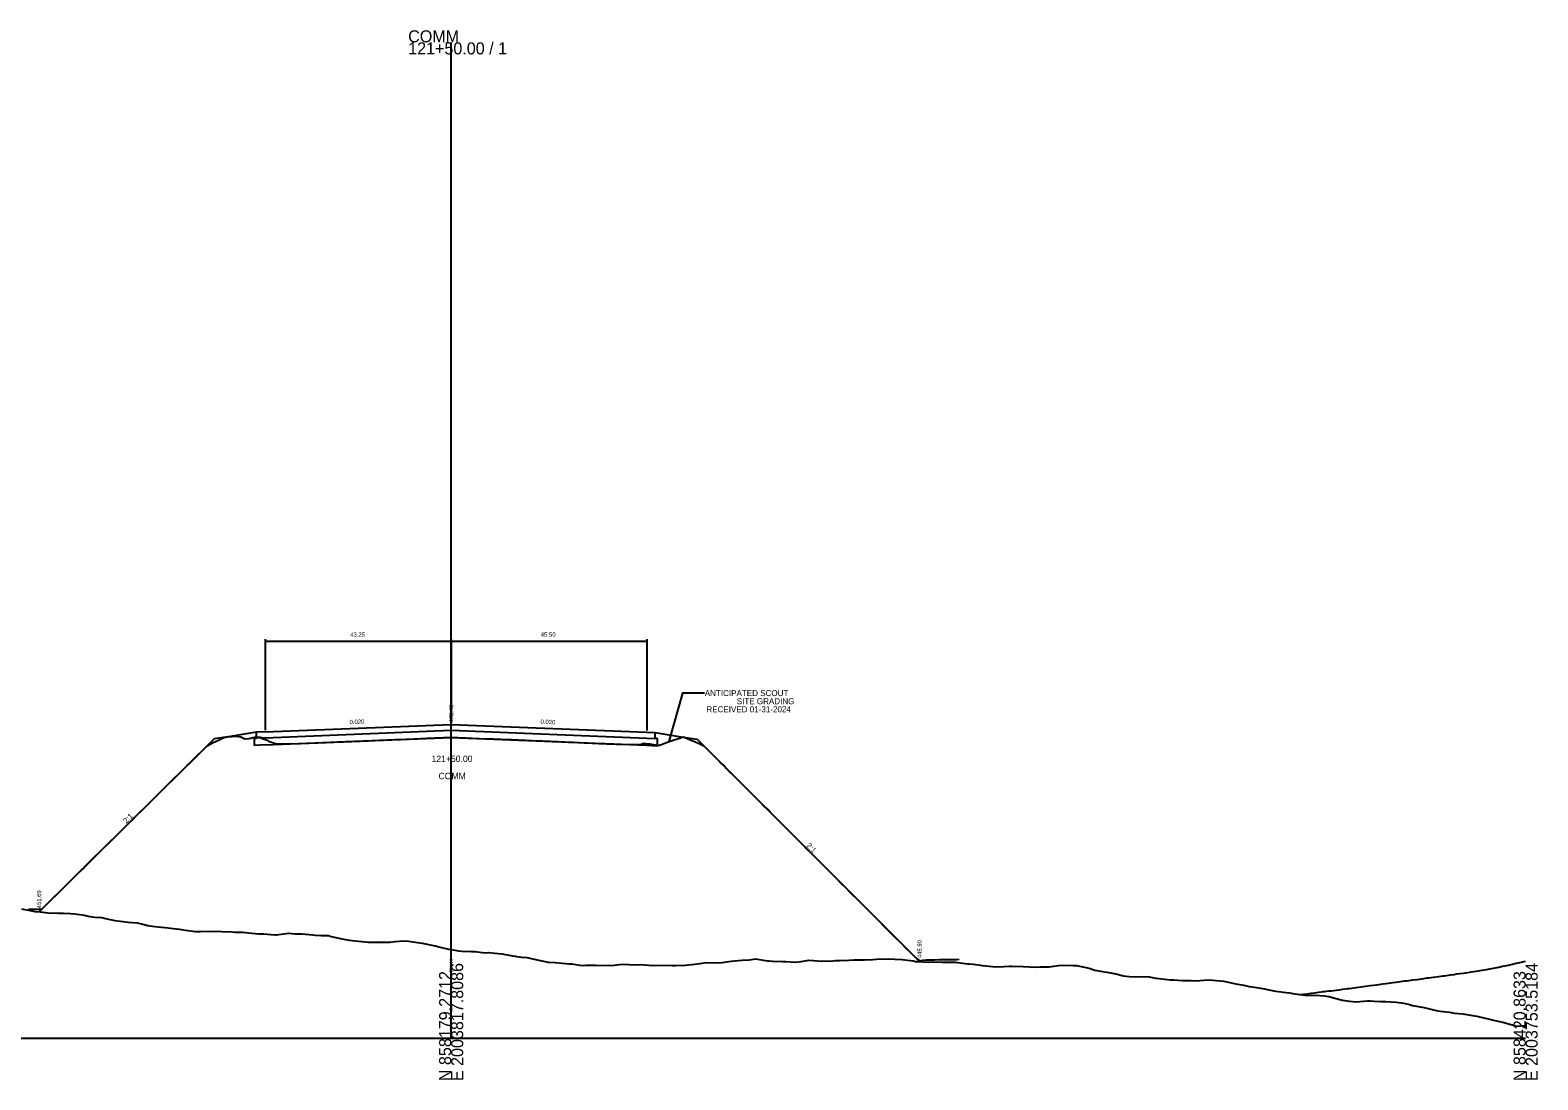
# Model space of a CAD drawing. Extents: x 2058594 to 2062449, y 841632 to 858028.
# Drawn here: x 2061098.6 to 2061449.4, y 855453.8 to 855698 of the extents above; entities that cross this region are included whole.
import ezdxf

# ---------------------------------------------------------------- set-up
doc = ezdxf.new("R2010")
doc.units = 0
for name, color, linetype in [('RD_DDB_Profile_Elev', 7, 'Continuous'), ('RD_GPK_XS_Cell', 7, 'Continuous'), ('RD_XS_Base', 7, 'Continuous'), ('RD_XS_EarthShd', 7, 'Continuous'), ('RD_XS_EwShp1', 7, 'Continuous'), ('RD_XS_ExGround', 7, 'Continuous'), ('RD_XS_Pave', 7, 'Continuous'), ('RD_XS_PaveShd', 7, 'Continuous'), ('RD_XS_TieSlope', 7, 'Continuous'), ('RD_XS_TX_Ditch', 7, 'Continuous'), ('RD_XS_TX_Elev_EX', 7, 'Continuous'), ('RD_XS_TX_Elev_PR', 7, 'Continuous'), ('RD_XS_TX_Misc', 7, 'Continuous'), ('RD_XS_TX_Slope', 7, 'Continuous'), ('RD_XS_TX_Station', 7, 'Continuous')]:
    doc.layers.add(name, color=color, linetype=linetype)

msp = doc.modelspace()

# ---------------------------------------------------------------- linework, layer by layer
at = {"layer": 'RD_DDB_Profile_Elev'}
for points in [[(2061255.47, 855543.83), (2061250.35, 855543.83), (2061247.13, 855532.52)], [(2061098.16, 855493.53), (2061099.26, 855493.53), (2061100.12, 855493.53), (2061101.24, 855493.53), (2061102.3, 855494.52), (2061103.27, 855495.53), (2061104.07, 855496.32), (2061105.29, 855497.53), (2061107.32, 855499.53), (2061108.7, 855500.89), (2061109.34, 855501.53), (2061110.86, 855503.03), (2061111.37, 855503.53), (2061113.4, 855505.53), (2061114.93, 855507.04), (2061115.42, 855507.53), (2061117.45, 855509.53), (2061119.47, 855511.53), (2061120.57, 855512.61), (2061121.5, 855513.53), (2061122.43, 855514.43), (2061123.52, 855515.53), (2061124.45, 855516.44), (2061125.55, 855517.53), (2061126.22, 855518.18), (2061127.58, 855519.53), (2061129.6, 855521.53), (2061131.63, 855523.53), (2061133.65, 855525.53), (2061135.11, 855526.97), (2061135.68, 855527.53), (2061136.61, 855528.45), (2061137.7, 855529.53), (2061139.73, 855531.53), (2061141.16, 855532.32), (2061142.21, 855532.8), (2061142.97, 855533.19), (2061143.79, 855533.53), (2061144.09, 855533.58), (2061144.48, 855533.65), (2061146.62, 855533.78), (2061147, 855533.71), (2061147.56, 855533.6), (2061148.51, 855533.13), (2061149.46, 855533.27), (2061149.88, 855533.35), (2061150.4, 855533.45), (2061150.82, 855533.53), (2061152.05, 855533.53), (2061152.7, 855533.15), (2061153.53, 855532.9), (2061154.04, 855532.66), (2061155.86, 855532.04), (2061156.74, 855532.02), (2061158.41, 855532), (2061161.08, 855532.07), (2061161.45, 855532.09), (2061162.89, 855532.15), (2061163.4, 855532.17), (2061164.76, 855532.22), (2061165.41, 855532.25), (2061166.62, 855532.3), (2061167.4, 855532.33), (2061168.41, 855532.37), (2061169.27, 855532.41), (2061170.06, 855532.44), (2061170.58, 855532.46), (2061171.47, 855532.5), (2061171.93, 855532.52), (2061172.8, 855532.56), (2061173.37, 855532.58), (2061174.01, 855532.61), (2061174.77, 855532.64), (2061175.34, 855532.66), (2061176, 855532.69), (2061176.59, 855532.72), (2061177.24, 855532.74), (2061178.09, 855532.78), (2061178.7, 855532.8), (2061179.78, 855532.85), (2061180.32, 855532.87), (2061181.61, 855532.92), (2061182.06, 855532.94), (2061183.5, 855533), (2061184.15, 855533.03), (2061186.05, 855533.11), (2061187.79, 855533.18), (2061189.45, 855533.25), (2061190.86, 855533.3), (2061191.72, 855533.34), (2061192.15, 855533.36), (2061192.75, 855533.38), (2061193.33, 855533.4), (2061194.09, 855533.42), (2061194.7, 855533.44), (2061195.76, 855533.47), (2061196.95, 855533.47), (2061198.01, 855533.45), (2061198.75, 855533.42), (2061199.95, 855533.38), (2061201.43, 855533.32), (2061203.04, 855533.26), (2061204.67, 855533.2), (2061206.45, 855533.13), (2061208.05, 855533.07), (2061209.17, 855533.03), (2061209.54, 855533.01), (2061210.44, 855532.98), (2061210.87, 855532.96), (2061211.52, 855532.93), (2061212.12, 855532.91), (2061212.61, 855532.89), (2061213.39, 855532.85), (2061213.91, 855532.83), (2061214.81, 855532.79), (2061215.35, 855532.77), (2061216.3, 855532.73), (2061216.83, 855532.71), (2061217.78, 855532.67), (2061218.26, 855532.65), (2061218.65, 855532.63), (2061219.56, 855532.59), (2061219.99, 855532.58), (2061220.59, 855532.55), (2061221.43, 855532.51), (2061222.2, 855532.48), (2061222.94, 855532.45), (2061223.85, 855532.41), (2061224.47, 855532.39), (2061224.97, 855532.36), (2061225.99, 855532.32), (2061226.34, 855532.31), (2061227.45, 855532.26), (2061227.78, 855532.25), (2061228.2, 855532.23), (2061229.32, 855532.18), (2061229.78, 855532.16), (2061230.86, 855532.12), (2061231.32, 855532.1), (2061232.29, 855532.06), (2061232.72, 855532.04), (2061233.49, 855532.01), (2061234, 855531.99), (2061234.38, 855531.97), (2061234.98, 855531.95), (2061235.82, 855531.91), (2061236.13, 855531.9), (2061237.37, 855531.85), (2061240.74, 855531.89), (2061241.37, 855532.18), (2061241.84, 855532.11), (2061242.75, 855531.97), (2061244.74, 855531.61), (2061245.11, 855531.75), (2061245.46, 855531.87), (2061246.58, 855532.31), (2061247.67, 855532.73), (2061250.54, 855533.63), (2061252.32, 855532.89), (2061252.63, 855532.74), (2061252.97, 855532.59), (2061254.2, 855532.05), (2061254.66, 855531.83), (2061255.29, 855531.53), (2061256.17, 855530.68), (2061256.56, 855530.28), (2061257.29, 855529.53), (2061258.12, 855528.73), (2061258.51, 855528.33), (2061259.29, 855527.53), (2061260.08, 855526.78), (2061260.46, 855526.38), (2061261.29, 855525.53), (2061262.04, 855524.81), (2061262.42, 855524.41), (2061263.29, 855523.53), (2061264.01, 855522.84), (2061264.4, 855522.44), (2061265.29, 855521.53), (2061266.25, 855520.59), (2061267.29, 855519.53), (2061268.45, 855518.39), (2061269.29, 855517.53), (2061270.39, 855516.46), (2061271.29, 855515.53), (2061272.04, 855514.81), (2061273.29, 855513.53), (2061274.46, 855512.4), (2061275.29, 855511.53), (2061276.23, 855510.62), (2061277.29, 855509.53), (2061278.27, 855508.57), (2061279.29, 855507.53), (2061280.3, 855506.54), (2061281.29, 855505.53), (2061282.24, 855504.6), (2061283.29, 855503.53), (2061284.27, 855502.57), (2061285.29, 855501.53), (2061286.12, 855500.72), (2061287.29, 855499.53), (2061288.33, 855498.49), (2061289.29, 855497.53), (2061291.29, 855495.53), (2061293.29, 855493.53), (2061295.29, 855491.53), (2061295.92, 855490.9), (2061297.29, 855489.53), (2061299.29, 855487.53), (2061301.29, 855485.53), (2061302.26, 855484.56), (2061303.29, 855483.53), (2061304.69, 855482.15), (2061305.54, 855481.53), (2061306.29, 855481.66), (2061307.03, 855481.72), (2061308.03, 855481.73), (2061309, 855481.79), (2061310.13, 855481.8), (2061311.24, 855481.81), (2061312.3, 855481.8), (2061313.04, 855481.83), (2061313.58, 855481.85), (2061314.07, 855481.87), (2061314.73, 855481.89)], [(2061393.65, 855473.71), (2061395.77, 855473.88), (2061396.15, 855473.93), (2061396.64, 855474), (2061396.98, 855474.03), (2061397.49, 855474.11), (2061397.93, 855474.17), (2061398.34, 855474.21), (2061398.91, 855474.28), (2061399.4, 855474.35), (2061399.83, 855474.39), (2061400.2, 855474.43), (2061400.83, 855474.51), (2061401.25, 855474.56), (2061401.9, 855474.65), (2061402.54, 855474.73), (2061403.12, 855474.8), (2061403.98, 855474.91), (2061405.14, 855475.07), (2061405.52, 855475.12), (2061407.12, 855475.33), (2061408.73, 855475.54), (2061410.36, 855475.76), (2061411.87, 855475.97), (2061412.84, 855476.1), (2061413.29, 855476.16), (2061414.02, 855476.26), (2061414.64, 855476.34), (2061415.14, 855476.41), (2061415.58, 855476.46), (2061416.39, 855476.57), (2061416.89, 855476.63), (2061417.87, 855476.77), (2061418.36, 855476.83), (2061418.81, 855476.89), (2061419.85, 855477.03), (2061420.19, 855477.07), (2061421.24, 855477.21), (2061422.39, 855477.37), (2061423.22, 855477.48), (2061423.59, 855477.53), (2061424.01, 855477.58), (2061425.06, 855477.72), (2061426.27, 855477.88), (2061427.3, 855478.02), (2061427.62, 855478.06), (2061428.58, 855478.19), (2061429.05, 855478.26), (2061429.89, 855478.37), (2061430.53, 855478.47), (2061431.22, 855478.56), (2061432.02, 855478.68), (2061432.55, 855478.76), (2061433.5, 855478.9), (2061433.85, 855478.96), (2061435.11, 855479.15), (2061436.37, 855479.36), (2061437.4, 855479.53), (2061438.19, 855479.66), (2061439.06, 855479.83), (2061439.91, 855480), (2061440.26, 855480.07), (2061441.14, 855480.25), (2061441.74, 855480.38), (2061442.52, 855480.55), (2061443.44, 855480.75), (2061444.01, 855480.87), (2061445.56, 855481.2), (2061446.51, 855481.41)]]:
    msp.add_lwpolyline(points, dxfattribs=at)
at = {"layer": 'RD_GPK_XS_Cell'}
for p, q in [((2061196.51, 855463.53), (2061196.51, 855695.2)), ((2060946.51, 855463.53), (2061196.51, 855463.53)), ((2061196.51, 855463.53), (2061446.51, 855463.53))]:
    msp.add_line(p, q, dxfattribs=at)
at = {"layer": 'RD_XS_Base'}
for p, q in [((2061150.74, 855533.3), (2061151.24, 855533.34)), ((2061150.74, 855531.63), (2061150.74, 855533.3)), ((2061153.27, 855531.75), (2061150.74, 855531.63)), ((2061153.27, 855531.75), (2061196.51, 855533.48)), ((2061196.51, 855533.48), (2061242.01, 855531.66)), ((2061242.01, 855531.66), (2061244.51, 855531.54)), ((2061244.51, 855533.21), (2061244.01, 855533.25)), ((2061244.51, 855531.54), (2061244.51, 855533.21))]:
    msp.add_line(p, q, dxfattribs=at)
at = {"layer": 'RD_XS_EarthShd'}
for p, q in [((2061151.24, 855534.71), (2061145.17, 855533.75)), ((2061244.01, 855534.62), (2061250.01, 855533.66))]:
    msp.add_line(p, q, dxfattribs=at)
at = {"layer": 'RD_XS_EwShp1'}
for p, q in [((2061151.24, 855534.71), (2061145.17, 855533.75)), ((2061151.24, 855533.34), (2061151.24, 855534.71)), ((2061244.01, 855533.25), (2061244.01, 855534.62)), ((2061244.01, 855534.62), (2061250.01, 855533.66)), ((2061141.37, 855533.15), (2061100.62, 855492.91)), ((2061145.17, 855533.75), (2061141.37, 855533.15)), ((2061150.74, 855533.3), (2061151.24, 855533.34)), ((2061150.74, 855531.63), (2061150.74, 855533.3)), ((2061153.27, 855531.75), (2061150.74, 855531.63)), ((2061153.27, 855531.75), (2061196.51, 855533.48)), ((2061196.51, 855533.48), (2061242.01, 855531.66)), ((2061242.01, 855531.66), (2061244.51, 855531.54)), ((2061244.51, 855533.21), (2061244.01, 855533.25)), ((2061244.51, 855531.54), (2061244.51, 855533.21)), ((2061250.01, 855533.66), (2061253.76, 855533.06)), ((2061253.76, 855533.06), (2061305.49, 855481.33))]:
    msp.add_line(p, q, dxfattribs=at)
at = {"layer": 'RD_XS_ExGround'}
msp.add_lwpolyline([(2061096.54, 855493.63), (2061098.93, 855493.13), (2061099.65, 855492.97), (2061100.89, 855492.9), (2061102.75, 855492.68), (2061105.12, 855492.64), (2061105.86, 855492.61), (2061106.29, 855492.61), (2061107.91, 855492.51), (2061108.96, 855492.46), (2061111.19, 855492.14), (2061112.07, 855491.94), (2061113.58, 855491.7), (2061115.17, 855491.62), (2061116.1, 855491.38), (2061118.28, 855490.92), (2061119.58, 855490.74), (2061121.38, 855490.53), (2061123.46, 855490.38), (2061124.49, 855490.12), (2061125.91, 855489.76), (2061127.59, 855489.52), (2061130.7, 855489.2), (2061131.24, 855489.13), (2061133.27, 855488.91), (2061133.8, 855488.84), (2061134.73, 855488.66), (2061136.91, 855488.34), (2061138.17, 855488.32), (2061140.01, 855488.44), (2061143.12, 855488.34), (2061145.53, 855488.29), (2061146.22, 855488.21), (2061147.98, 855488.21), (2061149.33, 855488.04), (2061151.66, 855487.84), (2061152.43, 855487.82), (2061152.89, 855487.77), (2061154.58, 855487.65), (2061155.54, 855487.6), (2061155.89, 855487.6), (2061158.64, 855487.98), (2061160.24, 855487.77), (2061161.75, 855487.78), (2061164.35, 855487.55), (2061164.85, 855487.5), (2061166.25, 855487.4), (2061167.96, 855487.38), (2061168.58, 855487.16), (2061171.06, 855486.63), (2061172.81, 855486.34), (2061174.17, 855486.14), (2061177.27, 855485.9), (2061177.92, 855485.9), (2061180.38, 855485.85), (2061182.31, 855485.86), (2061183.48, 855486.05), (2061185.5, 855486.14), (2061186.59, 855486.13), (2061189.73, 855485.62), (2061192.8, 855484.98), (2061193.96, 855484.67), (2061195.9, 855484.26), (2061196.51, 855484.14), (2061198.2, 855483.81), (2061199.01, 855483.76), (2061201.25, 855483.71), (2061202.11, 855483.67), (2061204.38, 855483.37), (2061205.22, 855483.48), (2061206.66, 855483.27), (2061208.32, 855483.15), (2061210.89, 855482.68), (2061211.43, 855482.57), (2061211.74, 855482.53), (2061212.92, 855482.41), (2061214.19, 855482.26), (2061214.53, 855482.19), (2061215.12, 855482.06), (2061217.64, 855481.49), (2061219.1, 855481.24), (2061220.74, 855481.13), (2061224, 855480.86), (2061224.59, 855480.79), (2061226.46, 855480.53), (2061226.95, 855480.45), (2061227.81, 855480.53), (2061230.06, 855480.5), (2061232.04, 855480.4), (2061233.16, 855480.49), (2061233.81, 855480.44), (2061236.27, 855480.73), (2061239.37, 855480.61), (2061240.5, 855480.63), (2061242.48, 855480.52), (2061243.62, 855480.47), (2061245.58, 855480.49), (2061247.92, 855480.47), (2061248.69, 855480.47), (2061250.98, 855480.55), (2061251.79, 855480.61), (2061253.2, 855480.72), (2061254.9, 855480.94), (2061255.88, 855481.11), (2061258, 855481.03), (2061259.59, 855481.16), (2061261.11, 855481.36), (2061261.66, 855481.41), (2061264.21, 855481.65), (2061265.89, 855481.75), (2061267.32, 855482.01), (2061270.12, 855481.56), (2061270.42, 855481.53), (2061271.26, 855481.45), (2061273.53, 855481.39), (2061274.35, 855481.36), (2061276.63, 855481.2), (2061277.96, 855481.38), (2061279.74, 855481.69), (2061282.93, 855481.45), (2061285.31, 855481.54), (2061285.95, 855481.58), (2061287.04, 855481.62), (2061289.05, 855481.66), (2061290.22, 855481.77), (2061292.16, 855481.74), (2061292.67, 855481.74), (2061294.6, 855481.87), (2061295.51, 855481.91), (2061298.37, 855482), (2061299.74, 855481.89), (2061301.47, 855481.85), (2061303.97, 855481.51), (2061304.58, 855481.4), (2061304.93, 855481.38), (2061306.26, 855481.28), (2061307.68, 855481.21), (2061308.2, 855481.25), (2061310.79, 855481.23), (2061312.43, 855481.24), (2061313.89, 855481.22), (2061316.66, 855480.82), (2061317, 855480.83), (2061317.93, 855480.71), (2061319.65, 855480.51), (2061320.1, 855480.43), (2061320.89, 855480.38), (2061323.21, 855480.11), (2061325.12, 855480.19), (2061326.31, 855480.29), (2061327, 855480.27), (2061329.6, 855480.17), (2061332.52, 855480.04), (2061333.58, 855480.14), (2061335.63, 855480.12), (2061337.81, 855480.47), (2061338.73, 855480.54), (2061341.27, 855480.47), (2061342.04, 855480.41), (2061344.94, 855479.82), (2061346.28, 855479.36), (2061348.05, 855479.03), (2061349.07, 855478.91), (2061351.15, 855478.49), (2061352.93, 855478.07), (2061354.26, 855477.84), (2061356.43, 855477.8), (2061357.36, 855477.85), (2061358.88, 855477.81), (2061360.47, 855477.5), (2061363.2, 855477.19), (2061363.79, 855477.12), (2061364.6, 855477.08), (2061366.68, 855476.92), (2061368.69, 855476.95), (2061369.78, 855476.88), (2061371.66, 855477.04), (2061372.89, 855477.09), (2061376.27, 855476.81), (2061379.1, 855476.15), (2061380.96, 855475.84), (2061382.2, 855475.55), (2061383.41, 855475.42), (2061385.31, 855475.08), (2061387.94, 855474.55), (2061388.41, 855474.46), (2061390.76, 855474.15), (2061391.52, 855474.07), (2061392.81, 855473.87), (2061394.62, 855473.58), (2061395.67, 855473.42), (2061397.73, 855473.57), (2061399.61, 855473.35), (2061400.83, 855473.19), (2061401.28, 855473.09), (2061403.94, 855472.39), (2061405.51, 855472.15), (2061407.04, 855472), (2061409.74, 855472.18), (2061410.38, 855472.2), (2061411.27, 855472.17), (2061412.84, 855472.09), (2061413.25, 855472.08), (2061413.97, 855472.03), (2061416.36, 855471.94), (2061418.2, 855471.64), (2061419.46, 855471.38), (2061420.19, 855471.15), (2061422.94, 855470.67), (2061425.67, 855470), (2061426.66, 855469.85), (2061428.78, 855469.59), (2061430, 855469.33), (2061431.88, 855469.17), (2061434.61, 855468.74), (2061435.12, 855468.64), (2061438.09, 855467.92), (2061439.35, 855467.62), (2061441.2, 855467.22), (2061443.58, 855466.53), (2061444.3, 855466.36), (2061446.51, 855466.46)], dxfattribs=at)
at = {"layer": 'RD_XS_Pave'}
for p, q in [((2061153.27, 855534.79), (2061196.51, 855536.52)), ((2061153.27, 855533.42), (2061196.51, 855535.15)), ((2061196.51, 855536.52), (2061242.01, 855534.7)), ((2061196.51, 855535.15), (2061242.01, 855533.33))]:
    msp.add_line(p, q, dxfattribs=at)
at = {"layer": 'RD_XS_PaveShd'}
for p, q in [((2061153.27, 855534.79), (2061151.24, 855534.71)), ((2061151.24, 855533.34), (2061151.24, 855534.71)), ((2061242.01, 855534.7), (2061244.01, 855534.62)), ((2061244.01, 855533.25), (2061244.01, 855534.62)), ((2061153.27, 855533.42), (2061151.24, 855533.34)), ((2061242.01, 855533.33), (2061244.01, 855533.25))]:
    msp.add_line(p, q, dxfattribs=at)
at = {"layer": 'RD_XS_TieSlope'}
for p, q in [((2061141.37, 855533.15), (2061100.62, 855492.91)), ((2061145.17, 855533.75), (2061141.37, 855533.15)), ((2061250.01, 855533.66), (2061253.76, 855533.06)), ((2061253.76, 855533.06), (2061305.49, 855481.33))]:
    msp.add_line(p, q, dxfattribs=at)
at = {"layer": 'RD_XS_TX_Misc'}
for p, q in [((2061153.27, 855556.32), (2061153.27, 855535.19)), ((2061153.27, 855555.92), (2061196.51, 855555.92)), ((2061196.51, 855556.32), (2061196.51, 855536.92)), ((2061196.51, 855555.92), (2061242.01, 855555.92)), ((2061242.01, 855556.32), (2061242.01, 855535.1))]:
    msp.add_line(p, q, dxfattribs=at)

# ---------------------------------------------------------------- texts
at = {"layer": 'RD_DDB_Profile_Elev'}
for s, p in [('ANTICIPATED SCOUT', (2061255.52, 855543.11)), ('SITE GRADING', (2061262.96, 855541.22)), ('RECEIVED 01-31-2024', (2061255.89, 855539.34))]:
    msp.add_text(s, height=1.4, dxfattribs=at).set_placement(p)
at = {"layer": 'RD_GPK_XS_Cell'}
for s, p in [('COMM', (2061186.51, 855695.2)), ('121+50.00 / 1', (2061186.51, 855692.4))]:
    msp.add_text(s, height=2.8, dxfattribs=at).set_placement(p)
for s, p in [('N 858179.2712', (2061196.51, 855453.53)), ('E 2003817.8086', (2061199.31, 855453.53)), ('N 858420.8633', (2061446.51, 855453.53)), ('E 2003753.5184', (2061449.31, 855453.53))]:
    msp.add_text(s, height=2.8, rotation=90, dxfattribs=at).set_placement(p)
at = {"layer": 'RD_XS_TX_Ditch'}
for s, p in [('451.69', (2061101.12, 855493.71)), ('445.90', (2061305.99, 855482.13))]:
    msp.add_text(s, height=1, rotation=90, dxfattribs=at).set_placement(p)
at = {"layer": 'RD_XS_TX_Elev_EX'}
msp.add_text('447.31', height=0.8, rotation=270, dxfattribs=at).set_placement((2061196.11, 855482.14))
at = {"layer": 'RD_XS_TX_Elev_PR'}
msp.add_text(' 473.49', height=1, rotation=90, dxfattribs=at).set_placement((2061197.01, 855536.52))
at = {"layer": 'RD_XS_TX_Misc'}
for s, p in [('43.25', (2061173.02, 855556.92)), ('45.50', (2061217.35, 855556.92))]:
    msp.add_text(s, height=1, dxfattribs=at).set_placement(p)
at = {"layer": 'RD_XS_TX_Slope'}
for s, height, rotation, p in [('0.020', 1, 2.2906, (2061172.89, 855536.57)), ('0.020', 1, 357.7094, (2061217.28, 855536.68)), ('2:1', 1.25, 44.6342, (2061120.91, 855513.39)), ('2:1', 1.25, 315, (2061279.05, 855508.22))]:
    msp.add_text(s, height=height, rotation=rotation, dxfattribs=at).set_placement(p)
at = {"layer": 'RD_XS_TX_Station'}
for s, p in [('121+50.00', (2061191.94, 855527.77)), ('COMM', (2061193.57, 855523.77))]:
    msp.add_text(s, height=1.5, dxfattribs=at).set_placement(p)

doc.saveas('drawing.dxf')
